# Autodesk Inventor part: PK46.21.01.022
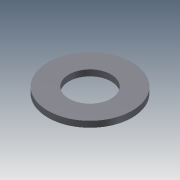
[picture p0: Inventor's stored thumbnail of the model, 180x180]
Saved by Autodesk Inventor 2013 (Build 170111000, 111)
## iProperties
Created: 2005-03
Part Number: PK46.21.01.022
Material: Steel, Mild
Document SubType Name: Modeling
Designer: salex
Manufacturer: Standard
Standards Organization: Custom
Density: 7.86 g/cm^3
Author: salex
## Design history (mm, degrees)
sketch "Эскиз1"
  geometry: C1 r 35 at (0, 0); C2 r 70 at (0, 0)
  constraints: 2 centre point, 1 coincident, 1 other
  dimensions: "d0" = 70 diameter of C1; "d1" = 140 diameter of C2
extrude "Выдавливание1" new body sketch "Эскиз1" distance "d2" = 10; taper "d3" = 0 deg
body "Solid1"
